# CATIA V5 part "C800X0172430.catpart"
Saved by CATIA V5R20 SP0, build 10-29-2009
Part number: C800X0172430
Source: Unknown
Property "A": "30"
Property "ARTICLENO": "C800X0172430"
Property "B": "13"
Property "BOMINFO": "C800X0172430"
Property "C": "46"
Property "CA": "C800X0172430"
Property "D1": "38"
Property "DES": "ROTATING EYEBOLT WITH RING Ton 1,7 M24x30"
Property "E": "50"
Property "H": "105"
Property "L": "30"
Property "LINA": "C800X0172430"
Property "NB": "C800X0172430"
Property "NBSYN": "$CODE."
Property "NN": "C800X"
Property "NT": "Rotating eyebolt with ring"
Property "SIZE": "M24"
Property "SUPPLIER": "CF"
Property "SW": "30"
Property "WEIGHT": "530"
Property "WLL": "1.70"
Bounding box of the stored display mesh (mm): x -27.837 to 28, y -30 to 117.837, z -19 to 19
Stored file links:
  C:\Users\Utente\Desktop\3D files 800X\C800X0172430.catpart
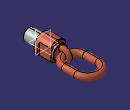
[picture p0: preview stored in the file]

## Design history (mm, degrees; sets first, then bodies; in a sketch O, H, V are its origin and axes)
Body1 "Geometry.1" (main body)
  Solid1 "C800X0172430.catpart": solid without history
